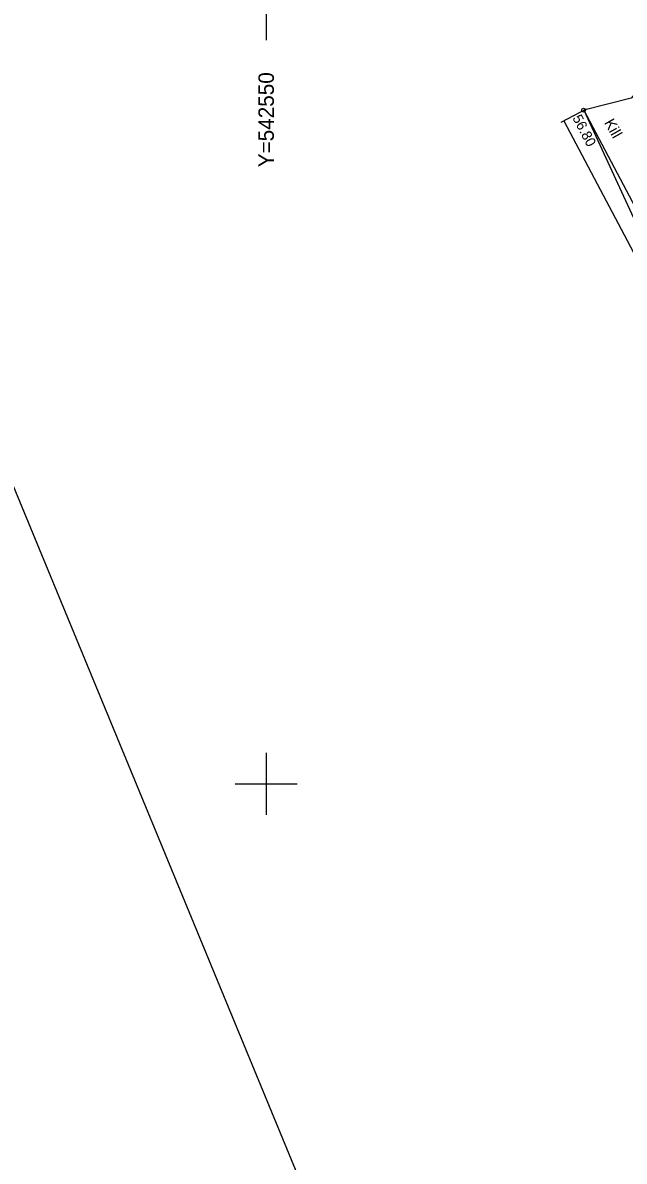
# Model space of a CAD drawing. Extents: x 542320 to 543602, y 6558748 to 6559969.
# Drawn here: x 542534.3 to 542573.1, y 6559275.6 to 6559349.1 of the extents above; entities that cross this region are included whole.
import ezdxf

# ---------------------------------------------------------------- set-up
doc = ezdxf.new("R2010")
doc.units = 0
for name, color, linetype in [('KORGUS-EH2000', 7, 'Continuous'), ('mootpiir', 7, 'Continuous'), ('PIIR', 7, 'Continuous'), ('RDT', 7, 'Continuous'), ('TEE', 7, 'Continuous'), ('VORK', 7, 'Continuous')]:
    doc.layers.add(name, color=color, linetype=linetype)

# ---------------------------------------------------------------- blocks, each defined once
blk = doc.blocks.new('VKORIS')
for p, q in [((0, 4), (0, -4)), ((-4, 0), (4, 0))]:
    blk.add_line(p, q)
blk = doc.blocks.new('RING02')
blk.add_circle((0, 0), 0.25)

msp = doc.modelspace()

# ---------------------------------------------------------------- linework, layer by layer
at = {"layer": 'mootpiir'}
msp.add_lwpolyline([(542580.596, 6559350.501), (542576.13, 6559347.213), (542573.572, 6559344.253), (542570.527, 6559343.48), (542613.7, 6559249.972), (542615.953, 6559250.584), (542618.546, 6559251.554), (542622.286, 6559253.49), (542626.884, 6559255.347), (542629.88, 6559255.645), (542630.445, 6559256.8), (542630.818, 6559257.341), (542632.786, 6559258.084), (542634.681, 6559258.868), (542635.466, 6559259.163), (542639.905, 6559261.019), (542642.325, 6559262.55), (542647.794, 6559265.185), (542644.803, 6559292.129), (542641.558, 6559300.605), (542636.848, 6559320.338), (542627.616, 6559356.728)], dxfattribs=at)
at = {"layer": 'PIIR'}
msp.add_lwpolyline([(542661.19, 6559057.3), (542631.86, 6559131.08), (542623.73, 6559151.51), (542622.55, 6559153.44), (542596.44, 6559196.28), (542582.74, 6559212.35), (542564.67, 6559244.2), (542533.12, 6559320.57), (542531.79, 6559323.45), (542465.95, 6559465.71), (542406.39, 6559583.67)], dxfattribs=at)
at = {"layer": 'RDT'}
for points in [[(542569.06, 6559342.703), (542570.704, 6559343.574)], [(542570.527, 6559343.48), (542587.317, 6559311.762), (542594.415, 6559298.323), (542600.925, 6559284.44), (542609.327, 6559263.254), (542613.7, 6559249.972)], [(542569.237, 6559342.797), (542586.027, 6559311.079), (542593.108, 6559297.672), (542599.584, 6559283.86), (542607.954, 6559262.756), (542612.313, 6559249.515)]]:
    msp.add_lwpolyline(points, dxfattribs=at)

# ---------------------------------------------------------------- block references
at = {"layer": 'KORGUS-EH2000', "xscale": 0.5, "yscale": 0.5}
msp.add_blockref('RING02', (542570.505, 6559343.483), dxfattribs=at)
at = {"layer": 'VORK', "xscale": 0.5, "yscale": 0.5}
for p in [(542550, 6559350), (542550, 6559300)]:
    msp.add_blockref('VKORIS', p, dxfattribs=at)

# ---------------------------------------------------------------- texts
at = {"layer": 'KORGUS-EH2000'}
msp.add_text('56.80', height=0.65, rotation=297.5172, dxfattribs=at).set_placement((542569.768, 6559342.983))
at = {"layer": 'TEE'}
msp.add_text('Kill', height=0.7, rotation=299.40818, dxfattribs=at).set_placement((542571.816, 6559342.682))
at = {"layer": 'VORK'}
msp.add_text('Y=542550', height=1, rotation=90, dxfattribs=at).set_placement((542550.502, 6559339.797))

doc.saveas('drawing.dxf')
